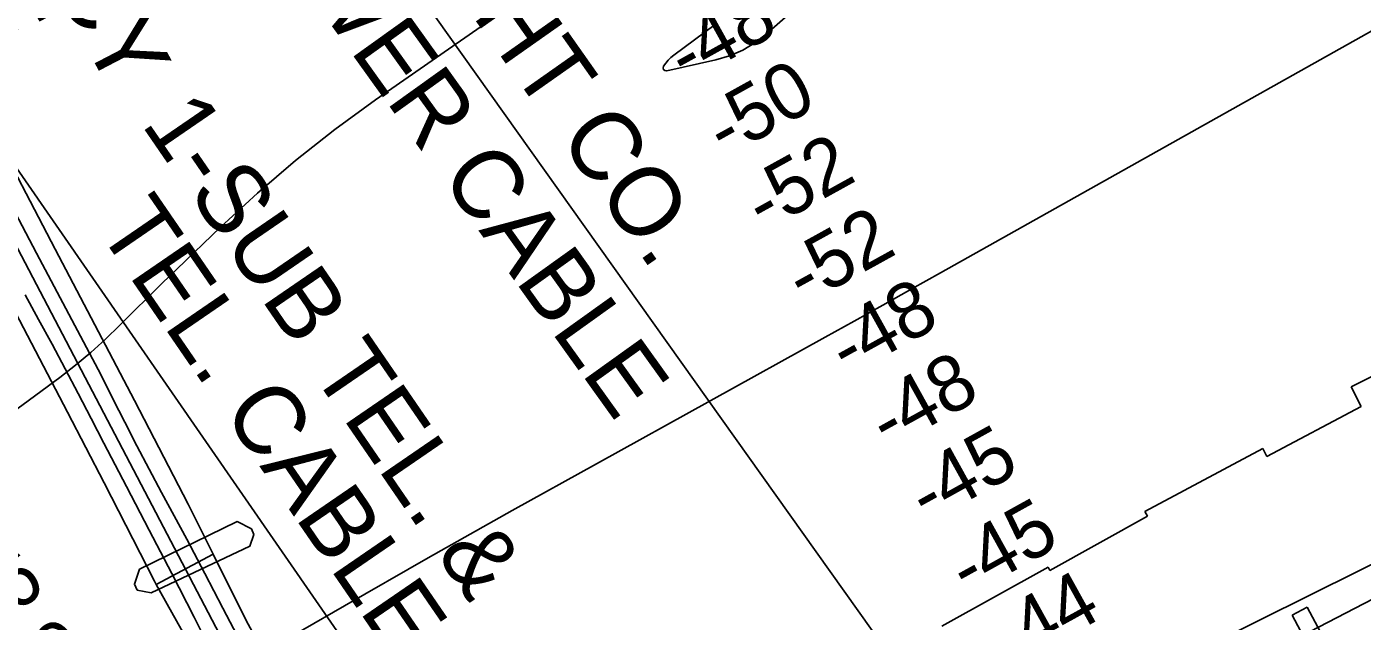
# Model space of a CAD drawing. Extents: x 3477039 to 3515015, y 546746 to 572297.
# Drawn here: x 3489880 to 3491478, y 562334 to 563045 of the extents above; entities that cross this region are included whole.
import ezdxf

# ---------------------------------------------------------------- set-up
doc = ezdxf.new("R2010")
doc.units = 0
for name, color, linetype in [('V-BRDG-IDEN', 7, 'Continuous'), ('V-BRDG-OTLN', 7, 'Continuous'), ('V-CHAN-DOCK', 7, 'Continuous'), ('V-CHAN-NAID', 7, 'Continuous'), ('V-RIVR-RANG', 7, 'Continuous'), ('V-ROAD-CNTR', 7, 'Continuous'), ('V-RRAP-RVMT', 7, 'Continuous'), ('V-TOPO-DPTH', 7, 'Continuous'), ('V-TOPO-MAJR', 7, 'Continuous'), ('V-TOPO-MINR', 7, 'Continuous'), ('V-UTIL-IDEN', 7, 'Continuous'), ('V-UTIL-LINE', 7, 'Continuous')]:
    doc.layers.add(name, color=color, linetype=linetype)

msp = doc.modelspace()

# ---------------------------------------------------------------- linework, layer by layer
at = {"layer": 'V-BRDG-OTLN'}
msp.add_lwpolyline([(3491569.5, 559533.5), (3491002.8, 560620), (3490594.8, 561392.2), (3490240.2, 562070.5), (3489765.9, 562976.2), (3489125.1, 564197.1), (3488755.5, 564911.6), (3488227.8, 565911.4), (3488087.8, 566206.4), (3488012.7, 566378.6), (3487979.4, 566462.3), (3487971, 566480.1)], dxfattribs=at)
for points in [[(3489359.7, 563673.8), (3489425.5, 563711.9), (3489500.9, 563564.1), (3489601.1, 563373.6), (3489674.4, 563232.6), (3489761.8, 563068.5), (3489834.2, 562931.4), (3489913.9, 562779.2), (3490009, 562598), (3490073.3, 562473.7), (3490103.1, 562413.8), (3490035, 562377.7), (3490032.8, 562381.7), (3489972.8, 562499.4), (3489928.7, 562584.1), (3489871.3, 562693.9), (3489826.3, 562779.4), (3489766.3, 562891.9), (3489699.9, 563024.1), (3489595.4, 563222.1), (3489529.8, 563346), (3489481.8, 563439), (3489420.1, 563557.2), (3489362.3, 563668.8)], [(3490035, 562377.7), (3490103.1, 562413.8), (3490142.2, 562335.3), (3490199.6, 562229.4), (3490256.2, 562120.1), (3490331.6, 561977.6), (3490374, 561896.1), (3490439, 561771.4), (3490466, 561719.5), (3490399.2, 561681.8), (3490354.1, 561765.7), (3490276.1, 561914.8), (3490207.9, 562043.1), (3490158.7, 562142.7), (3490089, 562280.7)]]:
    msp.add_lwpolyline(points, close=True, dxfattribs=at)
at = {"layer": 'V-CHAN-DOCK'}
msp.add_lwpolyline([(3490015.1, 562396.2), (3490132, 562453), (3490149, 562444.5), (3490151.8, 562437.5), (3490147, 562423.4), (3490028.8, 562367.9), (3490012.4, 562371), (3490009, 562378.1)], close=True, dxfattribs=at)
at = {"layer": 'V-ROAD-CNTR'}
for points in [[(3490403.3, 561794.5), (3490279.1, 562037.5), (3490245.7, 562100.1), (3490212.5, 562162.8), (3490179.4, 562225.6), (3490157.9, 562266.9), (3490136.4, 562308.2), (3490114.9, 562349.5), (3490093.3, 562390.8), (3490071.7, 562432), (3490056.4, 562459.8), (3490041.4, 562487.6), (3490026.5, 562515.6), (3490011.9, 562543.6), (3489997.4, 562571.8), (3489983.2, 562600.1), (3489969.1, 562628.4), (3489930.3, 562701.3), (3489891.7, 562774.2), (3489853.3, 562847.2)], [(3489878.1, 562724.4), (3489894.3, 562695), (3489910.3, 562665.5), (3489926.1, 562635.9), (3489941.7, 562606.3), (3489957.2, 562576.5), (3489972.5, 562546.7), (3489999.6, 562494.8), (3490026.7, 562442.8), (3490053.6, 562390.8), (3490080.5, 562338.7), (3490096.1, 562307.3)]]:
    msp.add_lwpolyline(points, dxfattribs=at)
at = {"layer": 'V-RRAP-RVMT'}
for p, q in [((3491465.1, 562614.1), (3491608.3, 562687.2)), ((3491476.9, 562590.9), (3491465.1, 562614.1)), ((3491364.2, 562531), (3491476.9, 562590.9)), ((3491218.1, 562465.2), (3491359.3, 562540.4)), ((3491359.3, 562540.4), (3491364.2, 562531)), ((3491221.2, 562459.4), (3491218.1, 562465.2)), ((3491104.3, 562394.5), (3491221.2, 562459.4)), ((3490975.3, 562327.9), (3491102.2, 562398.3)), ((3491102.2, 562398.3), (3491104.3, 562394.5)), ((3491412.4, 562350.7), (3491394.3, 562341.1)), ((3491394.3, 562341.1), (3491442.2, 562251.1)), ((3491460.3, 562260.7), (3491412.4, 562350.7))]:
    msp.add_line(p, q, dxfattribs=at)
at = {"layer": 'V-TOPO-DPTH'}
for points in [[(3489349.7, 561135.6), (3490038.4, 561564.6), (3490073.5, 561586.4), (3490108.7, 561608.1), (3490144, 561629.6), (3490179.3, 561651), (3490214.6, 561672.4), (3490249.9, 561693.9), (3490285.2, 561715.5), (3490320.4, 561737.1), (3491128.2, 562220.2), (3491164.7, 562239.4), (3491201.3, 562258.2), (3491238, 562276.7), (3492241.3, 562774.9)], [(3492241.3, 562774.9), (3491238, 562276.7), (3491201.3, 562258.2), (3491164.7, 562239.4), (3491128.2, 562220.2), (3490320.4, 561737.1), (3490285.2, 561715.5), (3490249.9, 561693.9), (3490214.6, 561672.4), (3490179.3, 561651), (3490144, 561629.6), (3490108.7, 561608.1), (3490073.5, 561586.4), (3490038.4, 561564.6), (3489349.7, 561135.6)], [(3489815, 561393.3), (3490246.9, 561652.1), (3490257.2, 561658.3), (3490267.4, 561664.5), (3490277.7, 561670.6), (3490288, 561676.8), (3490414.2, 561752.6), (3490487.7, 561796.4), (3490561.4, 561840.1), (3490635.2, 561883.3), (3490709.2, 561926.4), (3491151.9, 562182.4), (3491168.7, 562192), (3491185.6, 562201.4), (3491202.6, 562210.6), (3491219.7, 562219.6), (3491654.6, 562445)], [(3491654.6, 562445), (3491219.7, 562219.6), (3491202.6, 562210.6), (3491185.6, 562201.4), (3491168.7, 562192), (3491151.9, 562182.4), (3490709.2, 561926.4), (3490635.2, 561883.3), (3490561.4, 561840.1), (3490487.7, 561796.4), (3490414.2, 561752.6), (3490288, 561676.8), (3490277.7, 561670.6), (3490267.4, 561664.5), (3490257.2, 561658.3), (3490246.9, 561652.1), (3489815, 561393.3)]]:
    msp.add_lwpolyline(points, dxfattribs=at)
at = {"layer": 'V-TOPO-MAJR'}
for points in [[(3489548.2, 561897.6), (3489900, 562136.7), (3489931, 562157.3), (3489962.2, 562177.4), (3489993.8, 562196.9), (3490025.7, 562215.9), (3490160.7, 562294.6), (3490260.5, 562352.2), (3490360.6, 562409.5), (3490461, 562466.1), (3490561.7, 562522.2), (3490835.5, 562673.7), (3490870.1, 562692.9), (3490904.6, 562712.1), (3490939.1, 562731.4), (3490973.6, 562750.7), (3491986.7, 563319.7)], [(3490831.9, 563095.5), (3490765.2, 563036.6), (3490751.4, 563026.1), (3490736.8, 563017.2), (3490721.1, 563010.6), (3490704.6, 563005.6), (3490645.9, 562992.4), (3490643.6, 562992.9), (3490642, 562993.9), (3490641.6, 562995.7), (3490642, 562998.1), (3490644.7, 563001.8), (3490647.7, 563005.3), (3490651, 563008.4), (3490654.5, 563011.3), (3490704, 563048)]]:
    msp.add_lwpolyline(points, dxfattribs=at)
at = {"layer": 'V-TOPO-MINR'}
for points in [[(3489795.3, 562533.9), (3489919.6, 562625.5), (3489938.4, 562640.1), (3489956.8, 562655.2), (3489974.4, 562671.3), (3489991.5, 562687.9), (3490008.3, 562704.9), (3490025.2, 562721.7), (3490042.3, 562738.5), (3490059.5, 562755.1), (3490111.8, 562805.4), (3490156.1, 562846), (3490201.6, 562885.2), (3490248.9, 562922.1), (3490297.4, 562957.6), (3490579.1, 563153.8)], [(3489349.7, 561135.6), (3490038.4, 561564.6), (3490073.5, 561586.4), (3490108.7, 561608.1), (3490144, 561629.6), (3490179.3, 561651), (3490214.6, 561672.4), (3490249.9, 561693.9), (3490285.2, 561715.5), (3490320.4, 561737.1), (3491128.2, 562220.2), (3491164.7, 562239.4), (3491201.3, 562258.2), (3491238, 562276.7), (3492241.3, 562774.9)], [(3489815, 561393.3), (3490246.9, 561652.1), (3490257.2, 561658.3), (3490267.4, 561664.5), (3490277.7, 561670.6), (3490288, 561676.8), (3490414.2, 561752.6), (3490487.7, 561796.4), (3490561.4, 561840.1), (3490635.2, 561883.3), (3490709.2, 561926.4), (3491151.9, 562182.4), (3491168.7, 562192), (3491185.6, 562201.4), (3491202.6, 562210.6), (3491219.7, 562219.6), (3491654.6, 562445)]]:
    msp.add_lwpolyline(points, dxfattribs=at)
at = {"layer": 'V-UTIL-LINE'}
for points in [[(3489440.1, 564362), (3491200.1, 561889.4)], [(3489015.8, 564108), (3490723.2, 561639.9)]]:
    msp.add_lwpolyline(points, dxfattribs=at)

# ---------------------------------------------------------------- texts
at = {"layer": 'V-BRDG-IDEN'}
for s, p in [('GRAMERCY', (3489684.5, 563532.9)), ('BRIDGE', (3489636.3, 563388.4))]:
    msp.add_text(s, height=83, rotation=297.5361, dxfattribs=at).set_placement(p)
at = {"layer": 'V-CHAN-NAID'}
msp.add_text('CCI CARBON (145.6) (3)', height=100, rotation=292.0113, dxfattribs=at).set_placement((3491176.2, 564254.9))
at = {"layer": 'V-RIVR-RANG'}
for s, rotation, p in [('-48', 28.9616, (3490669.1, 562976.6)), ('-50', 28.9616, (3490715.3, 562887.8)), ('-52', 28.9616, (3490761.9, 562799.3)), ('-52', 28.9616, (3490810.1, 562711.7)), ('-48', 28.9616, (3490862, 562626.1)), ('-48', 28.9616, (3490910.2, 562538.5)), ('-45', 28.9616, (3490957.5, 562450.4)), ('-45', 28.9616, (3491005.7, 562362.8)), ('-56', 30.9036, (3489794.2, 562302.4)), ('-44', 28.9616, (3491055.5, 562276)), ('-49', 30.9036, (3489847.4, 562217.7))]:
    msp.add_text(s, height=67, rotation=rotation, dxfattribs=at).set_placement(p)
at = {"layer": 'V-UTIL-IDEN'}
for s, rotation, p in [('LA. POWER & LIGHT CO.', 305.1411, (3489876.3, 563820.8)), ('1-SUB POWER CABLE', 305.6303, (3489903, 563523.4)), ('1-SUB TEL. &', 304.4608, (3490016.4, 562928.7)), ('TEL. CABLE', 304.4608, (3489962.7, 562804.4))]:
    msp.add_text(s, height=83, rotation=rotation, dxfattribs=at).set_placement(p)

doc.saveas('drawing.dxf')
